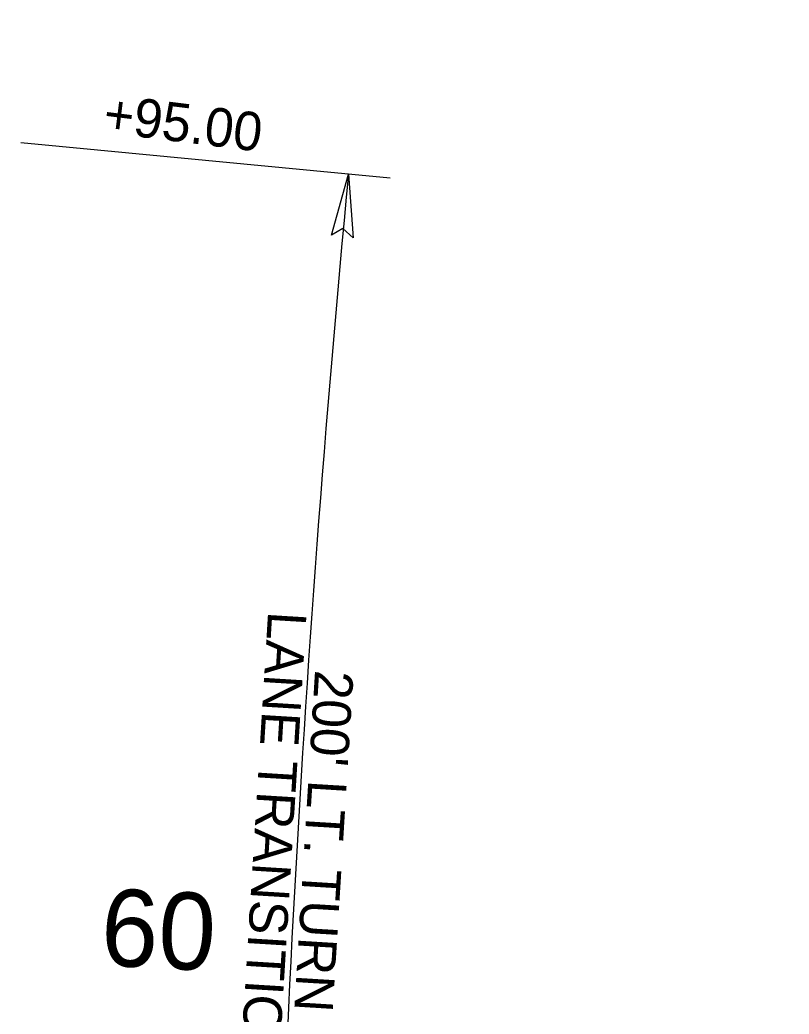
# Model space of a CAD drawing. Extents: x 1778969 to 1790720, y 807089 to 817794.
# Drawn here: x 1781029.2 to 1781129.1, y 811631.3 to 811760.3 of the extents above; entities that cross this region are included whole.
import ezdxf

# ---------------------------------------------------------------- set-up
doc = ezdxf.new("R2010")
doc.units = 0
for name, color, linetype in [('Prop Dimension', 7, 'Continuous'), ('Prop Dimension Text', 7, 'Continuous'), ('Prop EOT', 7, 'Continuous'), ('Prop Horizontal Alignment', 7, 'Continuous'), ('Prop Horizontal Alignment Tick Label', 7, 'Continuous'), ('Prop Lane Lines', 7, 'Continuous'), ('Prop Paved Shoulder', 7, 'Continuous'), ('Prop Terminator CELL', 7, 'Continuous')]:
    doc.layers.add(name, color=color, linetype=linetype)

msp = doc.modelspace()

# ---------------------------------------------------------------- linework, layer by layer
at = {"layer": 'Prop Dimension'}
msp.add_line((1781077.24, 811739.79), (1781029.29, 811744.39), dxfattribs=at)
msp.add_arc((1783331.44, 811523.22), 2270, 174.51216, 179.38099, dxfattribs=at)
at = {"layer": 'Prop EOT'}
msp.add_arc((1783308.81, 811525.98), 2309.25, 153.74801, 174.52695, dxfattribs=at)
at = {"layer": 'Prop Horizontal Alignment'}
msp.add_arc((1783308.81, 811525.98), 2330, 144.08998, 185.35942, dxfattribs=at)
at = {"layer": 'Prop Lane Lines'}
msp.add_arc((1783308.81, 811525.98), 2338.75, 165.86471, 174.52217, dxfattribs=at)
at = {"layer": 'Prop Paved Shoulder'}
msp.add_arc((1783308.81, 811525.98), 2305.25, 166.41947, 174.52695, dxfattribs=at)
at = {"layer": 'Prop Terminator CELL'}
msp.add_lwpolyline([(1781069.62, 811732.4), (1781071.85, 811740.31), (1781072.44, 811732.06), (1781071.11, 811733.24)], close=True, dxfattribs=at)

# ---------------------------------------------------------------- texts
at = {"layer": 'Prop Dimension Text'}
for s, rotation, p in [('+95.00', 352.9005, (1781039.83, 811745.76)), ('LANE TRANSITION', 266.4892, (1781061.41, 811683.63)), ("200' LT. TURN", 266.4892, (1781067.51, 811676))]:
    msp.add_text(s, height=5, rotation=rotation, dxfattribs=at).set_placement(p)
at = {"layer": 'Prop Horizontal Alignment Tick Label'}
msp.add_text('60', height=10, rotation=357.1089, dxfattribs=at).set_placement((1781039.5, 811637.62))

doc.saveas('drawing.dxf')
